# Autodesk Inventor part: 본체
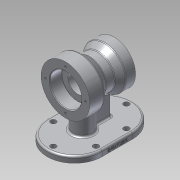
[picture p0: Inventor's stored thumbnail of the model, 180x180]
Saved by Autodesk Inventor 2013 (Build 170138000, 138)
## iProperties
Created: 2020-01
Part Number: 본체
Material: 알루미늄 6061
Document SubType Name: Modeling
Designer: Administrator
Density: 2.71 g/cm^3
Mass: 941.58 g
Surface Area: 654.878 cm^2
Volume: 347.446 cm^3
Author: Administrator
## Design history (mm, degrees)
sketch "스케치1"
  geometry: L1 (-40, 0)-(40, 0); L2 (-40, 0)-(-40, 26); L3 (-40, 40)-(-16, 40); L4 (-16, 40)-(-1.103, 27.5); L5 (-1.103, 27.5)-(13.289, 27.5); L6 (13.289, 27.5)-(24, 35); L7 (24, 35)-(40, 35); L8 (40, 35)-(40, 20); L9 (-40, 26)-(-20, 26); L10 (-20, 26)-(-20, 16); L11 (-20, 16)-(23, 16); L12 (23, 16)-(23, 20); L13 (23, 20)-(40, 20); L14 (-40, 26)-(-40, 40); L15 (40, 20)-(40, 0); 2 further points
  constraints: 30 end point, 6 parallel, 4 horizontal, 3 vertical, 2 perpendicular, 1 coincident, 1 midpoint
  dimensions: "d0" = 80 distance of L1.start L1.end; "d2" = 80 diameter of L3 L1; "d3" = 52 diameter of L9 L1; "d4" = 70 diameter of L7 L1; "d5" = 40 diameter of L13 L1; "d6" = 24 distance of L3.start L3.end; "d7" = 20 distance of L2.end L9.end; "d8" = 16 distance of L6.end L7.end; "d9" = 17 distance of L12.end L8.end; "d10" = 55 diameter of L5 L1; "d11" = 40 deg angle of L4 L5; "d12" = 35 deg angle of L6 L5; "d13" = 32 diameter of L11 L1
revolve "회전1" sketch "스케치1" stored, may be unused: angle "d14" = 90 deg
node "작업 평면1"
sketch "스케치2"
  geometry: L1 (-70, 45)-(70, 45); L2 (70, 45)-(70, -45); L3 (70, -45)-(-70, -45); L4 (-70, -45)-(-70, 45); L5 (-70, 45)-(70, -45); L6 (70, 45)-(-70, -45); 4 further points
  constraints: 12 end point, 4 midpoint, 2 coincident, 2 parallel, 1 horizontal, 1 perpendicular
  dimensions: "d16" = 140 distance of L2.end L3.end; "d18" = 90 distance of L3.end L1.start
extrude "돌출1" join sketch "스케치2" distance "d19" = 10; taper "d20" = 0 deg
fillet "모깎기1" dims "d21" = 45
sketch "스케치3" dims "d22" = 32
  geometry: L1 (3.199, 5)-(30, 5); L2 (30, 5)-(30, -5); L3 (30, -5)-(3.199, -5); L4 (3.199, -5)-(3.199, 5); L5 (3.199, 5)-(30, -5); L6 (30, 5)-(3.199, -5); A1 r 45 centre (-25, 0) between (-25, 45) and (-25, -45) reference; 5 further points
  constraints: 12 end point, 4 midpoint, 2 horizontal alignment, 2 parallel, 1 coincident, 1 horizontal, 1 perpendicular, 3 other
  dimensions: "d25" = 13 distance of A1.centre point (-12, 0); "d26" = 30 distance from line of L2 point (0, 0); "d27" = 10 distance of L1.end L2.end
extrude "돌출2" join sketch "스케치3" stored distance "d28" = 10; taper "d29" = 0 deg
sketch "스케치4"
  geometry: L1 (25, 45)-(-25, 45) reference; L2 (-25, -45)-(25, -45) reference; L3 (-25, 35)-(25, 35); L4 (25, -35)-(-25, -35); A1 r 45 centre (25, 0) between (25, -45) and (25, 45) reference; A2 r 45 centre (-25, 0) between (-25, 45) and (-25, -45) reference; A3 r 35 centre (25, 0) between (25, -35) and (25, 35); A4 r 35 centre (-25, 0) between (-25, 35) and (-25, -35); 7 further points
  constraints: 6 point on circle, 4 coincident, 4 end point, 2 centre point, 3 other
  dimensions: "d30" = 10 distance between parallel lines of L1 L3
hole "구멍1" sketch "스케치4" at (-25, 35), (25, 35), (25, -35), (-25, -35), (-60, 0), (60, 0) diameter "d31" = 9; stored, may be unused: countersink angle "d35" = 90 deg, drill point angle "d37" = 0 deg; dims "d32" = 6, "d33" = 4, "d34" = 2, "d36" = 8
sketch "스케치5"
  geometry: C1 r 40 at (0, 0) reference; 1 further point
  constraints: 1 vertical alignment
  dimensions: "d38" = 33 distance of C1.centre point (0, 33)
hole "구멍2" sketch "스케치5" at (0, 33) diameter "d39" = 3.242; stored, may be unused: countersink angle "d43" = 90 deg, drill point angle "d45" = 118 deg; dims "d40" = 9, "d41" = 4, "d42" = 2, "d44" = 11
sketch "스케치6"
  geometry: C1 r 20 at (0, 0) reference; 1 further point
  constraints: 1 vertical alignment
  dimensions: "d49" = 27.5 distance of C1.centre point (0, 27.5)
hole "구멍3" sketch "스케치6" at (0, 27.5) diameter "d50" = 3.242; stored, may be unused: countersink angle "d54" = 90 deg, drill point angle "d56" = 118 deg; dims "d51" = 9, "d52" = 4, "d53" = 2, "d55" = 11
chamfer "모따기1" distance "d60" = 1; stored, may be unused: second distance "d61" = 2, angle "d62" = 45 deg
fillet "모깎기2" dims "d63" = 0.3
fillet "모깎기3" dims "d64" = 3
fillet "모깎기4" dims "d65" = 3
fillet "모깎기5" dims "d66" = 3
fillet "모깎기6" dims "d67" = 3
fillet "모깎기7" dims "d68" = 3
sketch "스케치7"
  geometry: L1 (50, 0)-(0, 0) reference; L2 (-45, 0)-(-45, 7) reference; 2 further points
  constraints: 1 other
  dimensions: "d69" = 70 distance from line of point (25, 4) L2; "d70" = 4 distance from line of L1 point (25, 4)
feature "엠보싱1" sketch "스케치7" dims "d16" = 140, "d18" = 90, "d71" = 0.5, "d72" = 0
node "솔리드1"
pattern_circular "원형 패턴1" dims angle "d47" = 360 deg
pattern_circular "원형 패턴2" dims angle "d58" = 360 deg
